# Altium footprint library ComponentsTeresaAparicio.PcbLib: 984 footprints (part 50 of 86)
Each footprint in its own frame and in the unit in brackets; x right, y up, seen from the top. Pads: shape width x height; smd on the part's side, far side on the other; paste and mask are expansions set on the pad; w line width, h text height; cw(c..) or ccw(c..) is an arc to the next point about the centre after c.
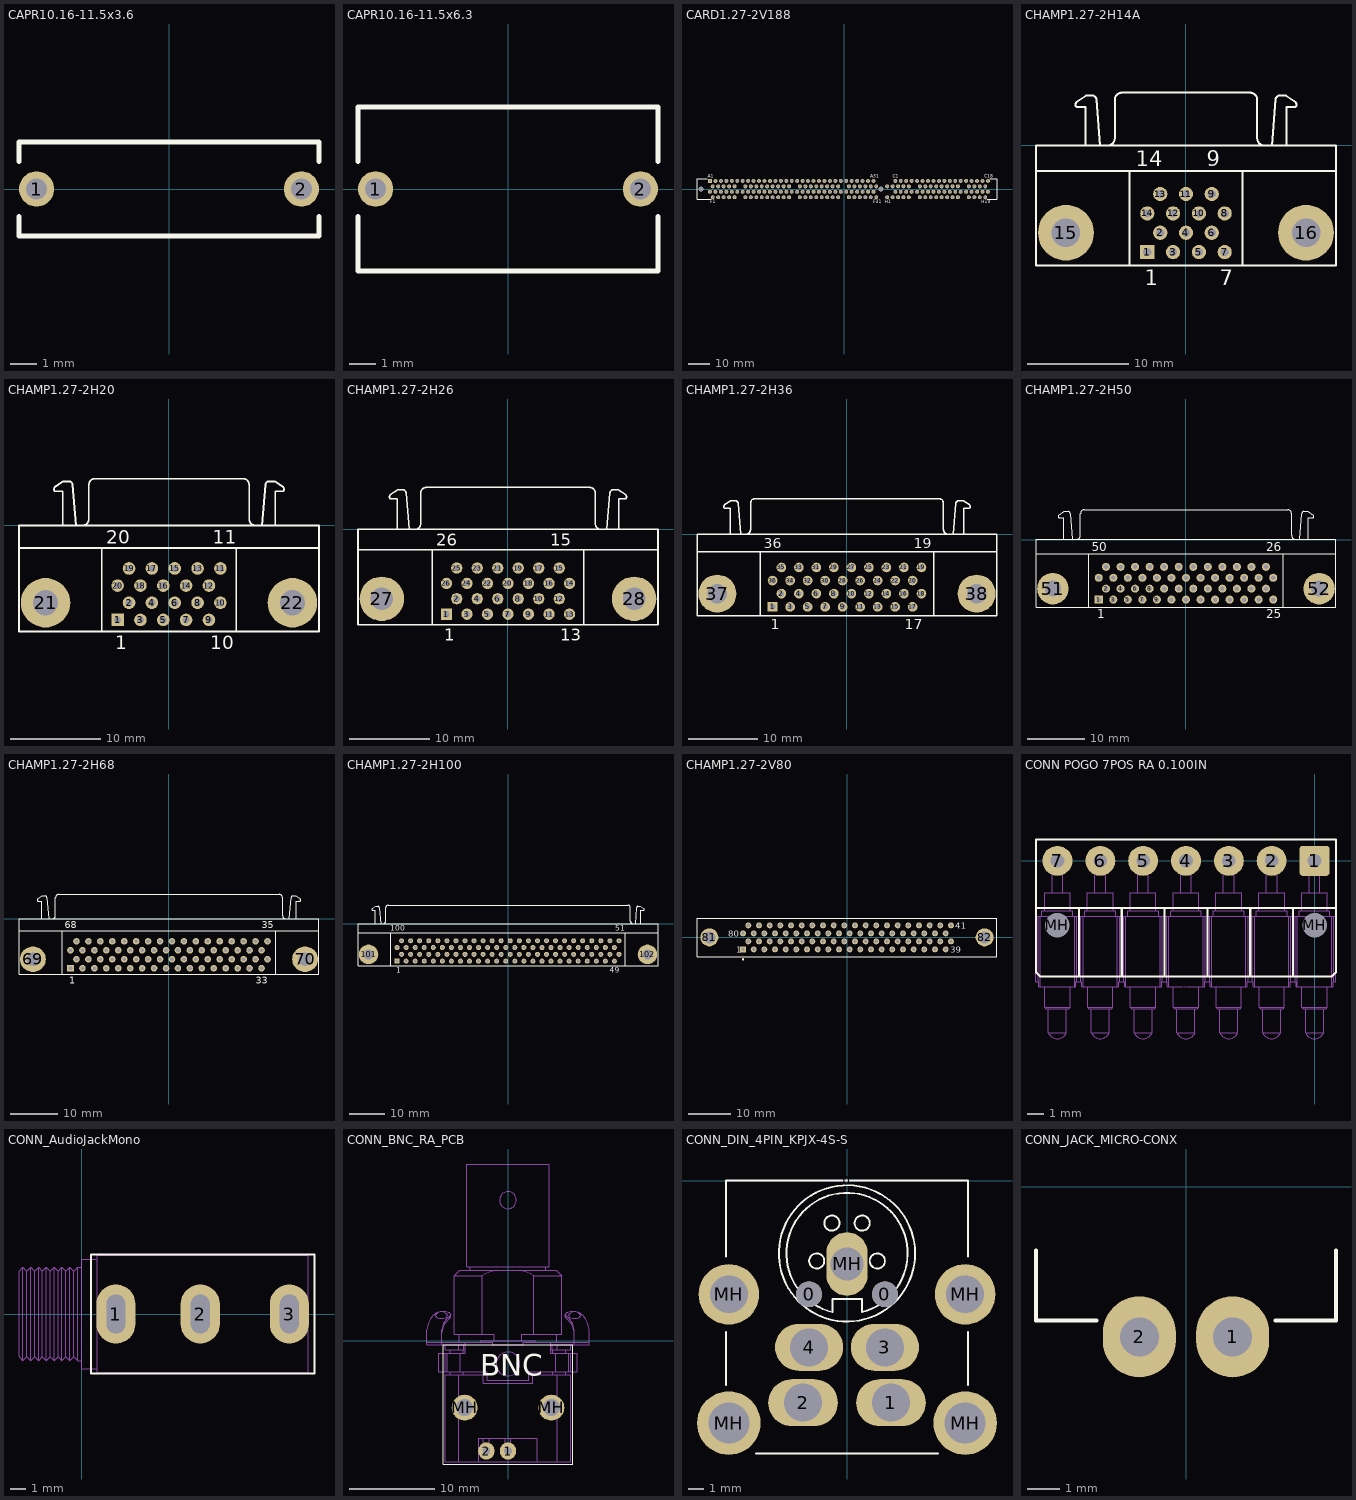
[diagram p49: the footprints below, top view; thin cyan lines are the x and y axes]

## CAPR10.16-11.5x3.6 [mm] "Capacitor, Ceramic, Thru-Hole, Dipped Radial; Body 11.5 x 3.6 mm (WxT) Pin Spacing 10.16 mm (typ)"
height 14.5
pads (2):
  round 1.35 hole 0.8: 1(-5.08,0) 2(5.08,0)
Top Overlay:
  lines w0.2: -5.75,-1.05 -5.75,-1.8 5.75,-1.8 5.75,-1.05 ; -5.75,1.05 -5.75,1.8 5.75,1.8 5.75,1.05

## CAPR10.16-11.5x6.3 [mm] "Capacitor, Ceramic, Thru-Hole, Dipped Radial; Body 11.5 x 6.3 mm (WxT) Pin Spacing 10.16 mm (typ)"
height 14.5
pads (2):
  round 1.35 hole 0.8: 1(-5.08,0) 2(5.08,0)
Top Overlay:
  lines w0.2: -5.75,-1.05 -5.75,-3.15 5.75,-3.15 5.75,-1.05 ; -5.75,1.05 -5.75,3.15 5.75,3.15 5.75,1.05

## CARD1.27-2V188 [mm] "Connector; EISA, Thru-Hole; 188 Position; Vertical; Pitch 1.27 mm"
height 15.49
pads (190):
  rect 1.85x1.85 hole 1.1: A1(-62.685,3.81)
  round 1.85 hole 1.1: A2(-60.145,3.81) A3(-57.605,3.81) A4(-55.065,3.81) A5(-52.525,3.81) A6(-49.985,3.81) A7(-47.445,3.81) A8(-44.905,3.81) A9(-42.365,3.81) A10(-39.825,3.81) A11(-37.285,3.81) A12(-34.745,3.81) A13(-32.205,3.81) A14(-29.665,3.81) A15(-27.125,3.81) A16(-24.585,3.81) A17(-22.045,3.81) A18(-19.505,3.81) A19(-16.965,3.81) A20(-14.425,3.81) A21(-11.885,3.81) A22(-9.345,3.81) A23(-6.805,3.81) A24(-4.265,3.81) A25(-1.725,3.81) A26(0.815,3.81) A27(3.355,3.81) A28(5.895,3.81) A29(8.435,3.81) A30(10.975,3.81) A31(13.515,3.81) B1(-62.685,-1.27) B2(-60.145,-1.27) B3(-57.605,-1.27) B4(-55.065,-1.27) B5(-52.525,-1.27) B6(-49.985,-1.27) B7(-47.445,-1.27) B8(-44.905,-1.27) B9(-42.365,-1.27) B10(-39.825,-1.27) B11(-37.285,-1.27) B12(-34.745,-1.27) B13(-32.205,-1.27) B14(-29.665,-1.27) B15(-27.125,-1.27) B16(-24.585,-1.27) B17(-22.045,-1.27) B18(-19.505,-1.27) B19(-16.965,-1.27) B20(-14.425,-1.27) B21(-11.885,-1.27) B22(-9.345,-1.27) B23(-6.805,-1.27) B24(-4.265,-1.27) B25(-1.725,-1.27) B26(0.815,-1.27) B27(3.355,-1.27) B28(5.895,-1.27) B29(8.435,-1.27) B30(10.975,-1.27) B31(13.515,-1.27) C1(23.675,3.81) C2(26.215,3.81) C3(28.755,3.81) C4(31.295,3.81) C5(33.835,3.81) C6(36.375,3.81) C7(38.915,3.81) C8(41.455,3.81) C9(43.995,3.81) C10(46.535,3.81) C11(49.075,3.81) C12(51.615,3.81) C13(54.155,3.81) C14(56.695,3.81) C15(59.235,3.81) C16(61.775,3.81) C17(64.315,3.81) C18(66.855,3.81) D1(23.675,-1.27) D2(26.215,-1.27) D3(28.755,-1.27) D4(31.295,-1.27) D5(33.835,-1.27) D6(36.375,-1.27) D7(38.915,-1.27) D8(41.455,-1.27) D9(43.995,-1.27) D10(46.535,-1.27) D11(49.075,-1.27) D12(51.615,-1.27) D13(54.155,-1.27) D14(56.695,-1.27) D15(59.235,-1.27) D16(61.775,-1.27) D17(64.315,-1.27) D18(66.855,-1.27) E1(-61.415,1.27) E2(-58.875,1.27) E3(-56.335,1.27) E4(-53.795,1.27) E5(-51.255,1.27) E7(-46.175,1.27) E8(-43.635,1.27) E9(-41.095,1.27) E10(-38.555,1.27) E11(-36.015,1.27) E12(-33.475,1.27) E13(-30.935,1.27) E14(-28.395,1.27) E15(-25.855,1.27) E17(-20.775,1.27) E18(-18.235,1.27) E19(-15.695,1.27) E20(-13.155,1.27) E21(-10.615,1.27) E22(-8.075,1.27) E23(-5.535,1.27) E24(-2.995,1.27) E26(2.085,1.27) E27(4.625,1.27) E28(7.165,1.27) E29(9.705,1.27) E30(12.245,1.27) E31(14.785,1.27) F1(-61.415,-3.81) F2(-58.875,-3.81) F3(-56.335,-3.81) F4(-53.795,-3.81) F5(-51.255,-3.81) F7(-46.175,-3.81) F8(-43.635,-3.81) F9(-41.095,-3.81) F10(-38.555,-3.81) F11(-36.015,-3.81) F12(-33.475,-3.81) F13(-30.935,-3.81) F14(-28.395,-3.81) F15(-25.855,-3.81) F17(-20.775,-3.81) F18(-18.235,-3.81) F19(-15.695,-3.81) F20(-13.155,-3.81) F21(-10.615,-3.81) F22(-8.075,-3.81) F23(-5.535,-3.81) F24(-2.995,-3.81) F26(2.085,-3.81) F27(4.625,-3.81) F28(7.165,-3.81) F29(9.705,-3.81) F30(12.245,-3.81) F31(14.785,-3.81) G1(19.865,1.27) G2(22.405,1.27) G3(24.945,1.27) G4(27.485,1.27) G5(30.025,1.27) G7(35.105,1.27) G8(37.645,1.27) G9(40.185,1.27) G10(42.725,1.27) G11(45.265,1.27) G12(47.805,1.27) G13(50.345,1.27) G14(52.885,1.27) G16(57.965,1.27) G17(60.505,1.27) G18(63.045,1.27) G19(65.585,1.27) H1(19.865,-3.81) H2(22.405,-3.81) H3(24.945,-3.81) H4(27.485,-3.81) H5(30.025,-3.81) H7(35.105,-3.81) H8(37.645,-3.81) H9(40.185,-3.81) H10(42.725,-3.81) H11(45.265,-3.81) H12(47.805,-3.81) H13(50.345,-3.81) H14(52.885,-3.81) H16(57.965,-3.81) H17(60.505,-3.81) H18(63.045,-3.81) H19(65.585,-3.81)
  round 2.14 hole 2.45: MH1(-66.855,0) MH2(16.965,0)
Top Overlay:
  lines w0.2: -64.06,4.76 -68.735,4.76 -68.735,-4.76 -62.345,-4.76 ; 66.515,-4.76 71.065,-4.76 71.065,4.76 67.785,4.76
  text "A1" at -63.785,5.26 h1.5
  text "A31" at 12.015,5.26 h1.5
  text "F31" at 13.285,-6.71 h1.5
  text "F1" at -62.515,-6.71 h1.5
  text "H1" at 18.765,-6.71 h1.5
  text "C1" at 22.575,5.26 h1.5
  text "H19" at 63.835,-6.71 h1.5
  text "C18" at 65.105,5.26 h1.5

## CHAMP1.27-2H14A [mm] "Connector; 14 Position; Right Angle; Pitch 1.27 mm"
height 9.6
pads (16):
  rect 1.4x1.4 hole 0.8: 1(-3.81,-10.5)
  round 1.4 hole 0.8: 2(-2.54,-8.595) 3(-1.27,-10.5) 4(0,-8.595) 5(1.27,-10.5) 6(2.54,-8.595) 7(3.81,-10.5) 8(3.81,-6.69) 9(2.54,-4.785) 10(1.27,-6.69) 11(0,-4.785) 12(-1.27,-6.69) 13(-2.54,-4.785) 14(-3.81,-6.69)
  round 5.5 hole 2.8: 15(-11.82,-8.595) 16(11.82,-8.595)
Top Overlay:
  lines w0.2: -14.77,-2.5 14.77,-2.5 ; -10.785,4.27 -9.845,4.898 -9.123,4.898 cw(c-9.225,4.5) -8.815,4.5 ; -10.771,4.255 ccw(c-10.545,4.01) -10.795,3.79 -9.915,3.79 -9.915,0 ; -8.815,4.52 -8.445,0 ; -7.705,0.005 ccw(c-7.705,0.7) -7.01,0.7 -7.01,4.5 ; -7.005,4.505 cw(c-6.31,4.505) -6.31,5.2 6.31,5.2 cw(c6.31,4.505) 7.005,4.505 ; -5.57,-11.8 -5.57,-2.58 ; 5.57,-11.8 5.57,-2.5 ; 7.01,4.5 7.01,0.7 ccw(c7.705,0.7) 7.705,0.005 ; 8.445,0 8.815,4.52 ; 8.815,4.5 cw(c9.225,4.5) 9.123,4.898 9.845,4.898 10.785,4.27 ; 9.915,0 9.915,3.79 10.795,3.79 ccw(c10.545,4.01) 10.771,4.255 ; -14.77,-11.8 14.77,-11.8 14.77,0 -14.77,0 -14.77,-11.8
  text "9" at 2.04,-2.025 h1.5
  text "14" at -4.935,-2.025 h1.5
  text "1" at -4.06,-13.775 h1.5
  text "7" at 3.31,-13.775 h1.5

## CHAMP1.27-2H20 [mm] "Connector; 20 Position; Right Angle; Pitch 1.27 mm"
height 9.6
pads (22):
  rect 1.4x1.4 hole 0.8: 1(-5.715,-10.5)
  round 1.4 hole 0.8: 2(-4.445,-8.595) 3(-3.175,-10.5) 4(-1.905,-8.595) 5(-0.635,-10.5) 6(0.635,-8.595) 7(1.905,-10.5) 8(3.175,-8.595) 9(4.445,-10.5) 10(5.715,-8.595) 11(5.715,-4.785) 12(4.445,-6.69) 13(3.175,-4.785) 14(1.905,-6.69) 15(0.635,-4.785) 16(-0.635,-6.69) 17(-1.905,-4.785) 18(-3.175,-6.69) 19(-4.445,-4.785) 20(-5.715,-6.69)
  round 5.5 hole 2.8: 21(-13.725,-8.595) 22(13.725,-8.595)
Top Overlay:
  lines w0.2: -16.675,-2.5 16.675,-2.5 ; -12.69,4.27 -11.75,4.898 -11.028,4.898 cw(c-11.13,4.5) -10.72,4.5 ; -12.676,4.255 ccw(c-12.45,4.01) -12.7,3.79 -11.82,3.79 -11.82,0 ; -10.72,4.52 -10.35,0 ; -9.61,0.005 ccw(c-9.61,0.7) -8.915,0.7 -8.915,4.5 ; -8.91,4.505 cw(c-8.215,4.505) -8.215,5.2 8.215,5.2 cw(c8.215,4.505) 8.91,4.505 ; -7.475,-11.8 -7.475,-2.58 ; 7.475,-11.8 7.475,-2.5 ; 8.915,4.5 8.915,0.7 ccw(c9.61,0.7) 9.61,0.005 ; 10.35,0 10.72,4.52 ; 10.72,4.5 cw(c11.13,4.5) 11.028,4.898 11.75,4.898 12.69,4.27 ; 11.82,0 11.82,3.79 12.7,3.79 ccw(c12.45,4.01) 12.676,4.255 ; -16.675,-11.8 16.675,-11.8 16.675,0 -16.675,0 -16.675,-11.8
  text "11" at 4.84,-2.025 h1.5
  text "20" at -6.965,-2.025 h1.5
  text "10" at 4.59,-13.775 h1.5
  text "1" at -5.965,-13.775 h1.5

## CHAMP1.27-2H26 [mm] "Connector; 26 Position; Right Angle; Pitch 1.27 mm"
height 9.6
pads (28):
  rect 1.4x1.4 hole 0.8: 1(-7.62,-10.5)
  round 1.4 hole 0.8: 2(-6.35,-8.595) 3(-5.08,-10.5) 4(-3.81,-8.595) 5(-2.54,-10.5) 6(-1.27,-8.595) 7(0,-10.5) 8(1.27,-8.595) 9(2.54,-10.5) 10(3.81,-8.595) 11(5.08,-10.5) 12(6.35,-8.595) 13(7.62,-10.5) 14(7.62,-6.69) 15(6.35,-4.785) 16(5.08,-6.69) 17(3.81,-4.785) 18(2.54,-6.69) 19(1.27,-4.785) 20(0,-6.69) 21(-1.27,-4.785) 22(-2.54,-6.69) 23(-3.81,-4.785) 24(-5.08,-6.69) 25(-6.35,-4.785) 26(-7.62,-6.69)
  round 5.5 hole 2.8: 27(-15.63,-8.595) 28(15.63,-8.595)
Top Overlay:
  lines w0.2: -18.58,-2.5 18.58,-2.5 ; -14.595,4.27 -13.655,4.898 -12.933,4.898 cw(c-13.035,4.5) -12.625,4.5 ; -14.581,4.255 ccw(c-14.355,4.01) -14.605,3.79 -13.725,3.79 -13.725,0 ; -12.625,4.52 -12.255,0 ; -11.515,0.005 ccw(c-11.515,0.7) -10.82,0.7 -10.82,4.5 ; -10.815,4.505 cw(c-10.12,4.505) -10.12,5.2 10.12,5.2 cw(c10.12,4.505) 10.815,4.505 ; -9.38,-11.8 -9.38,-2.58 ; 9.38,-11.8 9.38,-2.5 ; 10.82,4.5 10.82,0.7 ccw(c11.515,0.7) 11.515,0.005 ; 12.255,0 12.625,4.52 ; 12.625,4.5 cw(c13.035,4.5) 12.933,4.898 13.655,4.898 14.595,4.27 ; 13.725,0 13.725,3.79 14.605,3.79 ccw(c14.355,4.01) 14.581,4.255 ; -18.58,-11.8 -18.58,0 18.58,0 18.58,-11.8 -18.58,-11.8
  text "13" at 6.495,-13.775 h1.5
  text "26" at -8.87,-2.025 h1.5
  text "15" at 5.225,-2.025 h1.5
  text "1" at -7.87,-13.775 h1.5

## CHAMP1.27-2H36 [mm] "Connector; 36 Position; Right Angle; Pitch 1.27 mm"
height 9.6
pads (38):
  rect 1.4x1.4 hole 0.8: 1(-10.795,-10.5)
  round 1.4 hole 0.8: 2(-9.525,-8.595) 3(-8.255,-10.5) 4(-6.985,-8.595) 5(-5.715,-10.5) 6(-4.445,-8.595) 7(-3.175,-10.5) 8(-1.905,-8.595) 9(-0.635,-10.5) 10(0.635,-8.595) 11(1.905,-10.5) 12(3.175,-8.595) 13(4.445,-10.5) 14(5.715,-8.595) 15(6.985,-10.5) 16(8.255,-8.595) 17(9.525,-10.5) 18(10.795,-8.595) 19(10.795,-4.785) 20(9.525,-6.69) 21(8.255,-4.785) 22(6.985,-6.69) 23(5.715,-4.785) 24(4.445,-6.69) 25(3.175,-4.785) 26(1.905,-6.69) 27(0.635,-4.785) 28(-0.635,-6.69) 29(-1.905,-4.785) 30(-3.175,-6.69) 31(-4.445,-4.785) 32(-5.715,-6.69) 33(-6.985,-4.785) 34(-8.255,-6.69) 35(-9.525,-4.785) 36(-10.795,-6.69)
  round 5.5 hole 2.8: 37(-18.805,-8.595) 38(18.805,-8.595)
Top Overlay:
  lines w0.2: -21.755,-2.5 21.755,-2.5 ; -17.77,4.27 -16.83,4.898 -16.108,4.898 cw(c-16.21,4.5) -15.8,4.5 ; -17.756,4.255 ccw(c-17.53,4.01) -17.78,3.79 -16.9,3.79 -16.9,0 ; -15.8,4.52 -15.43,0 ; -14.69,0.005 ccw(c-14.69,0.7) -13.995,0.7 -13.995,4.5 ; -13.99,4.505 cw(c-13.295,4.505) -13.295,5.2 13.295,5.2 cw(c13.295,4.505) 13.99,4.505 ; -12.555,-11.8 -12.555,-2.58 ; 12.555,-11.8 12.555,-2.5 ; 13.995,4.5 13.995,0.7 ccw(c14.69,0.7) 14.69,0.005 ; 15.43,0 15.8,4.52 ; 15.8,4.5 cw(c16.21,4.5) 16.108,4.898 16.83,4.898 17.77,4.27 ; 16.9,0 16.9,3.79 17.78,3.79 ccw(c17.53,4.01) 17.756,4.255 ; -21.755,-11.8 21.755,-11.8 21.755,0 -21.755,0 -21.755,-11.8
  text "19" at 9.67,-2.025 h1.5
  text "36" at -12.045,-2.025 h1.5
  text "17" at 8.4,-13.775 h1.5
  text "1" at -11.045,-13.775 h1.5

## CHAMP1.27-2H50 [mm] "Connector; 50 Position; Right Angle; Pitch 1.27 mm"
height 9.6
pads (52):
  rect 1.4x1.4 hole 0.8: 1(-15.24,-10.477)
  round 1.4 hole 0.8: 2(-13.97,-8.572) 3(-12.7,-10.477) 4(-11.43,-8.572) 5(-10.16,-10.477) 6(-8.89,-8.572) 7(-7.62,-10.477) 8(-6.35,-8.572) 9(-5.08,-10.477) 10(-3.81,-8.572) 11(-2.54,-10.477) 12(-1.27,-8.572) 13(0,-10.477) 14(1.27,-8.572) 15(2.54,-10.477) 16(3.81,-8.572) 17(5.08,-10.477) 18(6.35,-8.572) 19(7.62,-10.477) 20(8.89,-8.572) 21(10.16,-10.477) 22(11.43,-8.572) 23(12.7,-10.477) 24(13.97,-8.572) 25(15.24,-10.477) 26(15.24,-6.667) 27(13.97,-4.763) 28(12.7,-6.667) 29(11.43,-4.763) 30(10.16,-6.667) 31(8.89,-4.763) 32(7.62,-6.667) 33(6.35,-4.763) 34(5.08,-6.667) 35(3.81,-4.763) 36(2.54,-6.667) 37(1.27,-4.763) 38(0,-6.667) 39(-1.27,-4.763) 40(-2.54,-6.667) 41(-3.81,-4.763) 42(-5.08,-6.667) 43(-6.35,-4.763) 44(-7.62,-6.667) 45(-8.89,-4.763) 46(-10.16,-6.667) 47(-11.43,-4.763) 48(-12.7,-6.667) 49(-13.97,-4.763) 50(-15.24,-6.667)
  round 5.5 hole 2.8: 51(-23.25,-8.572) 52(23.25,-8.572)
Top Overlay:
  lines w0.2: -26.2,-2.478 26.2,-2.478 ; -22.215,4.292 -21.275,4.92 -20.553,4.92 cw(c-20.655,4.523) -20.245,4.523 ; -22.201,4.277 ccw(c-21.975,4.032) -22.225,3.812 -21.345,3.813 -21.345,0.022 ; -20.245,4.543 -19.875,0.022 ; -19.135,0.028 ccw(c-19.135,0.723) -18.44,0.723 -18.44,4.523 ; -18.435,4.527 cw(c-17.74,4.527) -17.74,5.222 17.74,5.222 cw(c17.74,4.527) 18.435,4.527 ; -17,-11.777 -17,-2.558 ; 17,-11.777 17,-2.478 ; 18.44,4.523 18.44,0.723 ccw(c19.135,0.723) 19.135,0.028 ; 19.875,0.022 20.245,4.543 ; 20.245,4.523 cw(c20.655,4.523) 20.553,4.92 21.275,4.92 22.215,4.292 ; 21.345,0.022 21.345,3.812 22.225,3.813 ccw(c21.975,4.032) 22.201,4.277 ; -26.2,-11.777 -26.2,0.022 26.2,0.022 26.2,-11.777 -26.2,-11.777
  text "1" at -15.49,-13.752 h1.5
  text "25" at 13.99,-13.752 h1.5
  text "50" at -16.49,-2.003 h1.5
  text "26" at 13.99,-2.003 h1.5

## CHAMP1.27-2H68 [mm] "Connector; 68 Position; Right Angle; Pitch 1.27 mm"
height 9.6
pads (70):
  rect 1.4x1.4 hole 0.8: 1(-20.955,-10.5)
  round 1.4 hole 0.8: 2(-19.685,-8.595) 3(-18.415,-10.5) 4(-17.145,-8.595) 5(-15.875,-10.5) 6(-14.605,-8.595) 7(-13.335,-10.5) 8(-12.065,-8.595) 9(-10.795,-10.5) 10(-9.525,-8.595) 11(-8.255,-10.5) 12(-6.985,-8.595) 13(-5.715,-10.5) 14(-4.445,-8.595) 15(-3.175,-10.5) 16(-1.905,-8.595) 17(-0.635,-10.5) 18(0.635,-8.595) 19(1.905,-10.5) 20(3.175,-8.595) 21(4.445,-10.5) 22(5.715,-8.595) 23(6.985,-10.5) 24(8.255,-8.595) 25(9.525,-10.5) 26(10.795,-8.595) 27(12.065,-10.5) 28(13.335,-8.595) 29(14.605,-10.5) 30(15.875,-8.595) 31(17.145,-10.5) 32(18.415,-8.595) 33(19.685,-10.5) 34(20.955,-8.595) 35(20.955,-4.785) 36(19.685,-6.69) 37(18.415,-4.785) 38(17.145,-6.69) 39(15.875,-4.785) 40(14.605,-6.69) 41(13.335,-4.785) 42(12.065,-6.69) 43(10.795,-4.785) 44(9.525,-6.69) 45(8.255,-4.785) 46(6.985,-6.69) 47(5.715,-4.785) 48(4.445,-6.69) 49(3.175,-4.785) 50(1.905,-6.69) 51(0.635,-4.785) 52(-0.635,-6.69) 53(-1.905,-4.785) 54(-3.175,-6.69) 55(-4.445,-4.785) 56(-5.715,-6.69) 57(-6.985,-4.785) 58(-8.255,-6.69) 59(-9.525,-4.785) 60(-10.795,-6.69) 61(-12.065,-4.785) 62(-13.335,-6.69) 63(-14.605,-4.785) 64(-15.875,-6.69) 65(-17.145,-4.785) 66(-18.415,-6.69) 67(-19.685,-4.785) 68(-20.955,-6.69)
  round 5.5 hole 2.8: 69(-28.965,-8.595) 70(28.965,-8.595)
Top Overlay:
  lines w0.2: -31.915,-2.5 31.915,-2.5 ; -27.93,4.27 -26.99,4.898 -26.268,4.898 cw(c-26.37,4.5) -25.96,4.5 ; -27.916,4.255 ccw(c-27.69,4.01) -27.94,3.79 -27.06,3.79 -27.06,0 ; -25.96,4.52 -25.59,0 ; -24.85,0.005 ccw(c-24.85,0.7) -24.155,0.7 -24.155,4.5 ; -24.15,4.505 cw(c-23.455,4.505) -23.455,5.2 23.455,5.2 cw(c23.455,4.505) 24.15,4.505 ; -22.715,-11.8 -22.715,-2.58 ; 22.715,-11.8 22.715,-2.5 ; 24.155,4.5 24.155,0.7 ccw(c24.85,0.7) 24.85,0.005 ; 25.59,0 25.96,4.52 ; 25.96,4.5 cw(c26.37,4.5) 26.268,4.898 26.99,4.898 27.93,4.27 ; 27.06,0 27.06,3.79 27.94,3.79 ccw(c27.69,4.01) 27.916,4.255 ; -31.915,-11.8 -31.915,0 31.915,0 31.915,-11.8 -31.915,-11.8
  text "35" at 19.705,-2.025 h1.5
  text "68" at -22.205,-2.025 h1.5
  text "33" at 18.435,-13.775 h1.5
  text "1" at -21.205,-13.775 h1.5

## CHAMP1.27-2H100 [mm] "Connector; 100 Position; Right Angle; Pitch 1.27 mm"
height 9.6
pads (102):
  rect 1.4x1.4 hole 0.8: 1(-31.115,-10.5)
  round 1.4 hole 0.8: 2(-29.845,-8.595) 3(-28.575,-10.5) 4(-27.305,-8.595) 5(-26.035,-10.5) 6(-24.765,-8.595) 7(-23.495,-10.5) 8(-22.225,-8.595) 9(-20.955,-10.5) 10(-19.685,-8.595) 11(-18.415,-10.5) 12(-17.145,-8.595) 13(-15.875,-10.5) 14(-14.605,-8.595) 15(-13.335,-10.5) 16(-12.065,-8.595) 17(-10.795,-10.5) 18(-9.525,-8.595) 19(-8.255,-10.5) 20(-6.985,-8.595) 21(-5.715,-10.5) 22(-4.445,-8.595) 23(-3.175,-10.5) 24(-1.905,-8.595) 25(-0.635,-10.5) 26(0.635,-8.595) 27(1.905,-10.5) 28(3.175,-8.595) 29(4.445,-10.5) 30(5.715,-8.595) 31(6.985,-10.5) 32(8.255,-8.595) 33(9.525,-10.5) 34(10.795,-8.595) 35(12.065,-10.5) 36(13.335,-8.595) 37(14.605,-10.5) 38(15.875,-8.595) 39(17.145,-10.5) 40(18.415,-8.595) 41(19.685,-10.5) 42(20.955,-8.595) 43(22.225,-10.5) 44(23.495,-8.595) 45(24.765,-10.5) 46(26.035,-8.595) 47(27.305,-10.5) 48(28.575,-8.595) 49(29.845,-10.5) 50(31.115,-8.595) 51(31.115,-4.785) 52(29.845,-6.69) 53(28.575,-4.785) 54(27.305,-6.69) 55(26.035,-4.785) 56(24.765,-6.69) 57(23.495,-4.785) 58(22.225,-6.69) 59(20.955,-4.785) 60(19.685,-6.69) 61(18.415,-4.785) 62(17.145,-6.69) 63(15.875,-4.785) 64(14.605,-6.69) 65(13.335,-4.785) 66(12.065,-6.69) 67(10.795,-4.785) 68(9.525,-6.69) 69(8.255,-4.785) 70(6.985,-6.69) 71(5.715,-4.785) 72(4.445,-6.69) 73(3.175,-4.785) 74(1.905,-6.69) 75(0.635,-4.785) 76(-0.635,-6.69) 77(-1.905,-4.785) 78(-3.175,-6.69) 79(-4.445,-4.785) 80(-5.715,-6.69) 81(-6.985,-4.785) 82(-8.255,-6.69) 83(-9.525,-4.785) 84(-10.795,-6.69) 85(-12.065,-4.785) 86(-13.335,-6.69) 87(-14.605,-4.785) 88(-15.875,-6.69) 89(-17.145,-4.785) 90(-18.415,-6.69) 91(-19.685,-4.785) 92(-20.955,-6.69) 93(-22.225,-4.785) 94(-23.495,-6.69) 95(-24.765,-4.785) 96(-26.035,-6.69) 97(-27.305,-4.785) 98(-28.575,-6.69) 99(-29.845,-4.785) 100(-31.115,-6.69)
  round 5.5 hole 2.8: 101(-39.125,-8.595) 102(39.125,-8.595)
Top Overlay:
  lines w0.2: -42.075,-2.5 42.075,-2.5 ; -38.09,4.27 -37.15,4.898 -36.428,4.898 cw(c-36.53,4.5) -36.12,4.5 ; -38.076,4.255 ccw(c-37.85,4.01) -38.1,3.79 -37.22,3.79 -37.22,0 ; -36.12,4.52 -35.75,0 ; -35.01,0.005 ccw(c-35.01,0.7) -34.315,0.7 -34.315,4.5 ; -34.31,4.505 cw(c-33.615,4.505) -33.615,5.2 33.615,5.2 ; -32.875,-11.8 -32.875,-2.58 ; 32.875,-11.8 32.875,-2.5 ; 33.63,5.2 cw(c33.63,4.505) 34.325,4.505 ; 34.33,4.5 34.33,0.7 ccw(c35.025,0.7) 35.025,0.005 ; 35.765,0 36.135,4.52 ; 36.135,4.5 cw(c36.545,4.5) 36.443,4.898 37.165,4.898 38.105,4.27 ; 37.235,0 37.235,3.79 38.115,3.79 ccw(c37.865,4.01) 38.091,4.255 ; -42.075,-11.8 42.075,-11.8 42.075,0 -42.075,0 -42.075,-11.8
  text "51" at 30.115,-2.025 h1.5
  text "100" at -32.99,-2.025 h1.5
  text "49" at 28.595,-13.775 h1.5
  text "1" at -31.365,-13.775 h1.5

## CHAMP1.27-2V80 [mm] "Connector; 80 Position; Vertical; Pitch 1.27 mm"
height 11.1
pads (82):
  rect 1.4x1.4 hole 0.8: 1(-24.765,-2.857)
  round 1.4 hole 0.8: 2(-23.495,-0.953) 3(-22.225,-2.857) 4(-20.955,-0.953) 5(-19.685,-2.857) 6(-18.415,-0.953) 7(-17.145,-2.857) 8(-15.875,-0.953) 9(-14.605,-2.857) 10(-13.335,-0.953) 11(-12.065,-2.857) 12(-10.795,-0.953) 13(-9.525,-2.857) 14(-8.255,-0.953) 15(-6.985,-2.857) 16(-5.715,-0.953) 17(-4.445,-2.857) 18(-3.175,-0.953) 19(-1.905,-2.857) 20(-0.635,-0.953) 21(0.635,-2.857) 22(1.905,-0.953) 23(3.175,-2.857) 24(4.445,-0.953) 25(5.715,-2.857) 26(6.985,-0.953) 27(8.255,-2.857) 28(9.525,-0.953) 29(10.795,-2.857) 30(12.065,-0.953) 31(13.335,-2.857) 32(14.605,-0.953) 33(15.875,-2.857) 34(17.145,-0.953) 35(18.415,-2.857) 36(19.685,-0.953) 37(20.955,-2.857) 38(22.225,-0.953) 39(23.495,-2.857) 40(24.765,-0.953) 41(24.765,2.857) 42(23.495,0.953) 43(22.225,2.857) 44(20.955,0.953) 45(19.685,2.857) 46(18.415,0.953) 47(17.145,2.857) 48(15.875,0.953) 49(14.605,2.857) 50(13.335,0.953) 51(12.065,2.857) 52(10.795,0.953) 53(9.525,2.857) 54(8.255,0.953) 55(6.985,2.857) 56(5.715,0.953) 57(4.445,2.857) 58(3.175,0.953) 59(1.905,2.857) 60(0.635,0.953) 61(-0.635,2.857) 62(-1.905,0.953) 63(-3.175,2.857) 64(-4.445,0.953) 65(-5.715,2.857) 66(-6.985,0.953) 67(-8.255,2.857) 68(-9.525,0.953) 69(-10.795,2.857) 70(-12.065,0.953) 71(-13.335,2.857) 72(-14.605,0.953) 73(-15.875,2.857) 74(-17.145,0.953) 75(-18.415,2.857) 76(-19.685,0.953) 77(-20.955,2.857) 78(-22.225,0.953) 79(-23.495,2.857) 80(-24.765,0.953)
  round 4.3 hole 2.8: 81(-32.775,0) 82(32.775,0)
Top Overlay:
  circle w0.25: c-24.765,-5.25 r0.125
  lines w0.2: -35.725,-4.6 35.725,-4.6 35.725,4.6 -35.725,4.6 -35.725,-4.6
  text "41" at 25.84,2.107 h1.5
  text "80" at -28.34,0.202 h1.5
  text "39" at 24.57,-3.608 h1.5
  text "1" at -26.34,-3.608 h1.5

## CONN POGO 7POS RA 0.100IN [mil] "Connector; Pogo pins; 7 Position"
pads (10):
  round 20 on Mech14: 0(-300,-295)
  rrect20% 70x70 hole 32: 1(0,0)
  round 70 hole 32: 2(-100,0) 3(-200,0) 4(-300,0) 5(-400,0) 6(-500,0) 7(-600,0)
  round 55 hole 57 unplated: MH(-600,-150) MH(0,-150)
Top Overlay:
  lines w5: -650,-110 50,-110 ; -550,-270 -550,-110 ; -450,-270 -450,-110 ; -350,-270 -350,-110 ; -250,-270 -250,-110 ; -150,-270 -150,-110 ; -50,-270 -50,-110 ; -650,-260 -640,-270 40,-270 50,-260 50,50 -650,50 -650,-260
Mechanical 13:
  drawing of 200 lines, arcs and shapes, not listed
3D body: height 100, standoff -127, extent -649.99,-414.99 50.01,12.51

## CONN_AudioJackMono [mm] "CUI MJ-3502 3.5mm audio jack - mono"
height 11.3
pads (3):
  oval 2.5x3.8 hole 1.2 slot 2.5 at 90 deg: 1(2.2,0) 2(7.6,0) 3(13.3,0)
Top Overlay:
  lines w0.127: 0.6,-3.8 0.6,3.8 14.9,3.8 14.9,-3.8 0.6,-3.8
Mechanical 13:
  lines w0.05: 0,-3 -0.25,-3 ; 0,3 -0.25,3 ; 1,-3.5 0,-3.5 0,3.5 1,3.5 ; -3.75,-3 -4,-2.75 -4,2.75 -3.75,3 ; -3.75,-3 -3.5,-2.75 ; -3.75,-3 -3.75,3 ; -3.75,3 -3.5,2.75 ; -3.5,-2.75 -3.25,-3 ; -3.5,-2.75 -3.5,2.75 ; -3.5,2.75 -3.25,3 ; -3.25,-3 -3,-2.75 ; -3.25,-3 -3.25,3 ; -3.25,3 -3,2.75 ; -3,-2.75 -2.75,-3 ; -3,-2.75 -3,2.75 ; -3,2.75 -2.75,3 ; -2.75,-3 -2.5,-2.75 ; -2.75,-3 -2.75,3 ; -2.75,3 -2.5,2.75 ; -2.5,-2.75 -2.25,-3 ; -2.5,-2.75 -2.5,2.75 ; -2.5,2.75 -2.25,3 ; -2.25,-3 -2,-2.75 ; -2.25,-3 -2.25,3 ; -2.25,3 -2,2.75 ; -2,-2.75 -1.75,-3 ; -2,-2.75 -2,2.75 ; -2,2.75 -1.75,3 ; -1.75,-3 -1.5,-2.75 ; -1.75,-3 -1.75,3 ; -1.75,3 -1.5,2.75 ; -1.5,-2.75 -1.25,-3 ; -1.5,-2.75 -1.5,2.75 ; -1.5,2.75 -1.25,3 ; -1.25,-3 -1,-2.75 ; -1.25,-3 -1.25,3 ; -1.25,3 -1,2.75 ; -1,-2.75 -0.75,-3 ; -1,-2.75 -1,2.75 ; -1,2.75 -0.75,3 ; -0.75,-3 -0.5,-2.75 ; -0.75,-3 -0.75,3 ; -0.75,3 -0.5,2.75 ; -0.5,-2.75 -0.25,-3 ; -0.5,-2.75 -0.5,2.75 ; -0.5,2.75 -0.25,3 ; -0.25,-3 -0.25,3 ; 1,-3.75 14.5,-3.75 14.5,3.75 1,3.75 1,-3.75
3D body: height 11.3, standoff -4.1, extent -4,-3.75 14.5,3.75

## CONN_BNC_RA_PCB [mil] "BNC connector, right angle PCB-mounted"
height 530
pads (5):
  round 20 on Mech14: 0(0,0)
  oval 75x80 hole 35: 1(0,-510) 2(-100,-510)
  round 120 hole 79: MH(-200,-310) MH(200,-310)
Top Overlay:
  lines w5: -300,-570 300,-570 300,-20 -300,-20 -300,-570
  text "BNC" at -127.35,-163 h100
Mechanical 13:
  drawing of 173 lines, arcs and shapes, not listed
3D body: height 532, standoff -135, extent -375,-559.78 375,815.22

## CONN_DIN_4PIN_KPJX-4S-S [mm] "Power Connector, 4-pin DIN"
height 15
pads (12):
  round 1.7 hole 1.7 unplated: 0(-2.5,-7.5) 0(2.5,-7.5)
  round 1 on Mech14: 0(0,0)
  oval 4.6x3.1 hole 2.5: 1(2.9,-14.65) 2(-2.9,-14.65)
  oval 4.5x3.1 hole 2.5: 3(2.5,-11) 4(-2.5,-11)
  round 4.2 hole 2.7: MH(-7.8,-16) MH(7.8,-16)
  round 4 hole 2.5: MH(-7.8,-7.5) MH(7.8,-7.5)
  oval 2.7x4.2 hole 2.2: MH(0,-5.5)
Top Overlay:
  circle w0.127: c2,-5.3 r0.5
  circle w0.127: c-2,-5.3 r0.5
  circle w0.127: c-1,-2.8 r0.5
  circle w0.127: c1,-2.8 r0.5
  circle w0.127: c0,-4.8 r4.5
  lines w0.127: -8,-13.5 -8,-10 ; -8,-5 -8,0 8,0 8,-5 ; -6,-18 6,-18 ; 1,-8.671 1,-7.8 -0.97,-7.8 -0.97,-8.681 cw(c0,-4.8) 1.007,-8.671 ; 8,-13.5 8,-10
3D body: height 15.01, standoff -3.49, extent -8,-17.65 8,0

## CONN_JACK_MICRO-CONX [mil] "Micro-ConX 17292-2PG-300"
height 480
pads (2):
  oval 90x100 hole 48: 1(57.5,-185) 2(-57.5,-185)
Top Overlay:
  lines w5: -185,-78.74 -185,-165 -110.24,-165 ; 110.24,-165 185,-165 185,-78.74
3D body: height 476.88, standoff -146.88, extent -312.51,-205 310.03,547.5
